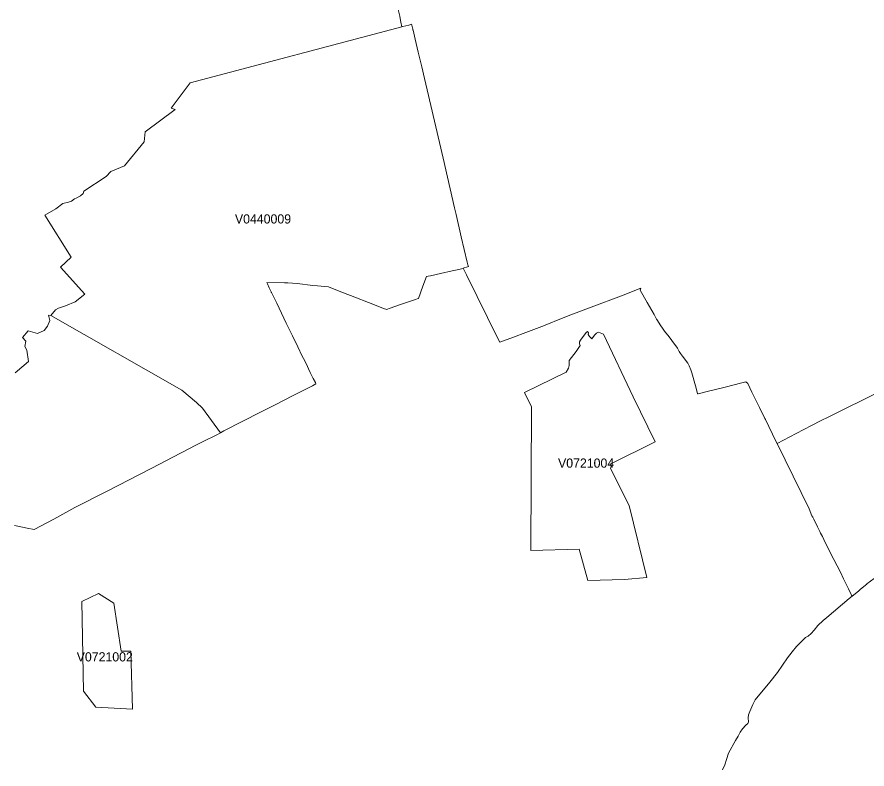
# Model space of a CAD drawing. Extents: x 369010 to 735936, y 6377141 to 6616555.
# Drawn here: x 389842 to 399077, y 6449862 to 6458030 of the extents above; entities that cross this region are included whole.
import ezdxf
from ezdxf.enums import TextEntityAlignment as Align

# ---------------------------------------------------------------- set-up
doc = ezdxf.new("R2010")
doc.units = 0
doc.header["$LTSCALE"] = 40
doc.layers.add('3', color=7, linetype='Continuous', lineweight=13)
doc.layers.add('4', color=7, linetype='Continuous')

msp = doc.modelspace()

# ---------------------------------------------------------------- linework, layer by layer
at = {"layer": '3'}
for points in [[(391559.8, 6457026.29), (391516.76, 6457038.21), (391722.82, 6457316.42), (394024.81, 6457924.48), (394013.06, 6457974.46), (394009.92, 6457990.68), (394000.81, 6458037.69), (393981.12, 6458125.24), (393959.6, 6458222.39), (393924.35, 6458376.31), (393879.17, 6458576.4), (393824.39, 6458815.89), (393782.35, 6459006.38), (393772.91, 6459047.59)], [(394000.81, 6458037.69), (394009.92, 6457990.68), (394013.06, 6457974.46), (394024.81, 6457924.48), (394024.81, 6457924.48), (394032.92, 6457926.3), (394097.63, 6457943.02), (394119.98, 6457949.14), (394129.74, 6457951.29), (394132.39, 6457942.03), (394142.82, 6457896.51), (394144.14, 6457890.88), (394144.97, 6457887.74), (394167.48, 6457790.75), (394201.24, 6457649.25), (394238.81, 6457489.21), (394268.6, 6457363.59), (394298.06, 6457239.46), (394470.51, 6456498.33), (394594.81, 6455955.98), (394612.68, 6455886.3), (394667.63, 6455641.19), (394732.84, 6455368.77), (394741.78, 6455337.16), (394746.57, 6455320.44), (394736.48, 6455316.47), (394690.63, 6455301.08), (394693.45, 6455295.62), (394725.06, 6455230.74), (395068.81, 6454532.64), (395087.18, 6454496.56), (395235.64, 6454551.01), (395370.19, 6454602.82), (395572.27, 6454679.61), (395581.21, 6454684.08), (395757.47, 6454754.25), (395859.09, 6454794.14), (396079.71, 6454878.71), (396409.39, 6455002.34), (396621.4, 6455083.44), (396611.31, 6455063.25), (396687.11, 6454930.68), (396763.41, 6454797.28), (396790.55, 6454749.12), (396794.02, 6454743.5), (396838.55, 6454674.81), (396855.26, 6454650.65), (396877.77, 6454617.88), (396925.77, 6454554.49), (396955.39, 6454517.75), (397017.46, 6454432.02), (397037.48, 6454398.09), (397050.22, 6454375.58), (397073.56, 6454345.29), (397130, 6454269)], [(394024.81, 6457924.48), (394024.81, 6457924.48), (391722.82, 6457316.42), (391516.76, 6457038.21), (391559.8, 6457026.29), (391233.26, 6456784.49), (391225.31, 6456672.61), (391009.33, 6456414.75), (390860.54, 6456352.53), (390811.06, 6456299.4), (390569.58, 6456138.03), (390561.14, 6456111.88), (390530.86, 6456087.39), (390485.18, 6456061.57), (390466.64, 6456053.63), (390434.86, 6456031.12), (390401.1, 6456017.21), (390338.38, 6456005.96), (390264.23, 6455947.7), (390143.41, 6455878.19), (390430.23, 6455423.05), (390313.88, 6455312.5), (390577.36, 6455018.89), (390475.41, 6454934.82), (390368.33, 6454891.12), (390292.37, 6454869.28), (390259.26, 6454848.76), (390209.78, 6454788.51), (391632.78, 6453976.05), (391793.49, 6453842.99), (391858.7, 6453780.1), (392053.33, 6453514.3), (392089.74, 6453534.16), (392493.07, 6453742.2), (392639.21, 6453815.35), (392843.78, 6453918.13), (393052.81, 6454025.54), (393090.54, 6454044.9), (393083.43, 6454058.47), (393060.92, 6454104.15), (393027.98, 6454169.86), (393008.29, 6454209.58), (392986.44, 6454257.74), (392953.84, 6454322.45), (392939.93, 6454347.61), (392892.1, 6454447.57), (392835, 6454567.4), (392767.31, 6454706.09), (392664.2, 6454920.75), (392606.61, 6455038.42), (392604.95, 6455042.06), (392603.79, 6455044.22), (392581.62, 6455089.4), (392561.92, 6455131.77), (392557.12, 6455144.84), (392747.29, 6455141.37), (392784.69, 6455141.53), (392885.32, 6455136.9), (393055.12, 6455114.72), (393107.42, 6455108.93), (393226.42, 6455097.51), (393358.66, 6455045.21), (393390.6, 6455033.13), (393512.08, 6454987.61), (393661.03, 6454928.86), (393742.63, 6454894.77), (393825.21, 6454864.48), (393858.81, 6454852.89), (393867.91, 6454856.04), (393886.45, 6454862.16), (394020.18, 6454909.99), (394160.19, 6454956.5), (394201.57, 6454971.56), (394203.39, 6454973.55), (394251.72, 6455108.27), (394291.94, 6455210.05), (394308.65, 6455213.53), (394335.46, 6455220.15), (394444.7, 6455244.64), (394569.49, 6455271.78), (394641.98, 6455288), (394670.44, 6455294.95), (394690.63, 6455301.08), (394736.48, 6455316.47), (394746.57, 6455320.44), (394741.78, 6455337.16), (394732.84, 6455368.77), (394667.63, 6455641.19), (394612.68, 6455886.3), (394594.81, 6455955.98), (394470.51, 6456498.33), (394298.06, 6457239.46), (394268.6, 6457363.59), (394238.81, 6457489.21), (394201.24, 6457649.25), (394167.48, 6457790.75), (394144.97, 6457887.74), (394144.14, 6457890.88), (394142.82, 6457896.51), (394132.39, 6457942.03)], [(394132.39, 6457942.03), (394129.74, 6457951.29), (394119.98, 6457949.14), (394097.63, 6457943.02), (394032.92, 6457926.3), (394024.81, 6457924.48)], [(389821.51, 6454163.73), (389967.65, 6454288.19), (389950.43, 6454412.65), (389928.75, 6454452.7), (389938.02, 6454508.31), (389903.6, 6454549.19), (389963.84, 6454622.02), (390063.64, 6454593.55), (390136.79, 6454624.17), (390173.86, 6454673.16), (390198.36, 6454732.08), (390185.78, 6454792.98), (390209.78, 6454788.51), (390259.26, 6454848.76), (390292.37, 6454869.28), (390368.33, 6454891.12), (390475.41, 6454934.82), (390577.36, 6455018.89), (390313.88, 6455312.5), (390430.23, 6455423.05), (390143.41, 6455878.19), (390264.23, 6455947.7), (390338.38, 6456005.96), (390401.1, 6456017.21), (390434.86, 6456031.12), (390466.64, 6456053.63), (390485.18, 6456061.57), (390530.86, 6456087.39), (390561.14, 6456111.88), (390569.58, 6456138.03), (390811.06, 6456299.4), (390860.54, 6456352.53), (391009.33, 6456414.75), (391225.31, 6456672.61), (391233.26, 6456784.49), (391559.8, 6457026.29)], [(398265.52, 6451135.18), (398309.88, 6451193.1), (398410.17, 6451291.25), (398436.65, 6451306.14), (398468.76, 6451334.61), (398501.53, 6451370.69), (398541.91, 6451419.68), (398599.01, 6451476.12), (398641.71, 6451509.55), (398882.19, 6451713.94), (398914.96, 6451739.76), (398909.83, 6451749.36), (398902.38, 6451763.26), (398874.24, 6451819.87), (398833.53, 6451904.61), (398822.44, 6451926.95), (398787.85, 6451998.45), (398715.2, 6452138.13), (398623.01, 6452321.68), (398591.56, 6452386.06), (398582.63, 6452404.43), (398573.36, 6452423.29), (398563.76, 6452442.99), (398554.33, 6452462.52), (398539.26, 6452493.14), (398523.87, 6452523.59), (398509.31, 6452552.06), (398497.39, 6452575.23), (398486.47, 6452596.91), (398479.02, 6452611.47), (398449.56, 6452686.94), (398100.02, 6453399.27), (398086.94, 6453424.59), (397973.9, 6453658.12), (397967.78, 6453670.04), (397908.86, 6453788.87), (397873.77, 6453862.02), (397827.27, 6453954.21), (397780.59, 6454050.03), (397759.41, 6454068.4), (397716.38, 6454056.65), (397534.32, 6454010.64), (397342.01, 6453961.32), (397243.2, 6453937.33), (397236.75, 6453935.84), (397229.3, 6453968.77), (397215.23, 6454024.55), (397174.35, 6454166.71), (397164.42, 6454196.34), (397145.89, 6454242.51), (397130, 6454269), (397073.56, 6454345.29), (397050.22, 6454375.58), (397037.48, 6454398.09), (397017.46, 6454432.02), (396955.39, 6454517.75), (396925.77, 6454554.49), (396877.77, 6454617.88), (396855.26, 6454650.65), (396838.55, 6454674.81), (396794.02, 6454743.5), (396790.55, 6454749.12), (396763.41, 6454797.28), (396687.11, 6454930.68), (396611.31, 6455063.25), (396621.4, 6455083.44), (396409.39, 6455002.34), (396079.71, 6454878.71), (395859.09, 6454794.14), (395757.47, 6454754.25), (395581.21, 6454684.08), (395572.27, 6454679.61), (395370.19, 6454602.82), (395235.64, 6454551.01), (395087.18, 6454496.56), (395068.81, 6454532.64), (394725.06, 6455230.74), (394693.45, 6455295.62), (394690.63, 6455301.08), (394670.44, 6455294.95), (394641.98, 6455288), (394569.49, 6455271.78), (394444.7, 6455244.64), (394335.46, 6455220.15), (394308.65, 6455213.53), (394291.94, 6455210.05), (394251.72, 6455108.27), (394203.39, 6454973.55), (394201.57, 6454971.56), (394160.19, 6454956.5), (394020.18, 6454909.99), (393886.45, 6454862.16), (393867.91, 6454856.04), (393858.81, 6454852.89), (393825.21, 6454864.48), (393742.63, 6454894.77), (393661.03, 6454928.86), (393512.08, 6454987.61), (393390.6, 6455033.13), (393358.66, 6455045.21)], [(393358.66, 6455045.21), (393226.42, 6455097.51), (393107.42, 6455108.93), (393055.12, 6455114.72), (392885.32, 6455136.9), (392784.69, 6455141.53), (392747.29, 6455141.37), (392557.12, 6455144.84), (392561.92, 6455131.77), (392581.62, 6455089.4), (392603.79, 6455044.22), (392604.95, 6455042.06), (392606.61, 6455038.42), (392664.2, 6454920.75), (392767.31, 6454706.09), (392835, 6454567.4), (392892.1, 6454447.57), (392939.93, 6454347.61), (392953.84, 6454322.45), (392986.44, 6454257.74), (393008.29, 6454209.58), (393027.98, 6454169.86), (393060.92, 6454104.15), (393083.43, 6454058.47), (393090.54, 6454044.9), (393052.81, 6454025.54), (392843.78, 6453918.13), (392639.21, 6453815.35), (392493.07, 6453742.2), (392089.74, 6453534.16), (392053.33, 6453514.3)], [(391863.16, 6453418.14), (392014.43, 6453492.95), (392053.33, 6453514.3), (391858.7, 6453780.1), (391793.49, 6453842.99), (391632.78, 6453976.05), (390209.78, 6454788.51), (390185.78, 6454792.98), (390198.36, 6454732.08), (390173.86, 6454673.16), (390136.79, 6454624.17), (390063.64, 6454593.55), (389963.84, 6454622.02), (389903.6, 6454549.19), (389938.02, 6454508.31), (389928.75, 6454452.7), (389950.43, 6454412.65), (389967.65, 6454288.19), (389821.51, 6454163.73)], [(397130, 6454269), (397145.89, 6454242.51), (397164.42, 6454196.34), (397174.35, 6454166.71), (397215.23, 6454024.55), (397229.3, 6453968.77), (397236.75, 6453935.84), (397243.2, 6453937.33), (397342.01, 6453961.32), (397534.32, 6454010.64), (397716.38, 6454056.65), (397759.41, 6454068.4), (397780.59, 6454050.03), (397827.27, 6453954.21), (397873.77, 6453862.02), (397908.86, 6453788.87), (397967.78, 6453670.04), (397973.9, 6453658.12), (398086.94, 6453424.59), (398100.02, 6453399.27), (398306.57, 6453507.68), (398472.4, 6453593.57), (398578.32, 6453646.7), (398655.28, 6453685.26), (399230.08, 6453970.76)], [(399230.08, 6453970.76), (398655.28, 6453685.26), (398578.32, 6453646.7), (398472.4, 6453593.57), (398306.57, 6453507.68), (398100.02, 6453399.27), (398449.56, 6452686.94), (398479.02, 6452611.47), (398486.47, 6452596.91), (398497.39, 6452575.23), (398509.31, 6452552.06), (398523.87, 6452523.59), (398539.26, 6452493.14), (398554.33, 6452462.52)], [(392053.33, 6453514.3), (392014.43, 6453492.95), (391863.16, 6453418.14), (391783.89, 6453380.4), (391632.78, 6453300.96), (391527.85, 6453247.34), (391396.94, 6453177.66), (391291.68, 6453121.56), (390819.99, 6452881.08), (390471.94, 6452701.34), (390439.33, 6452684.63), (390241.89, 6452577.21), (390030.37, 6452464.01), (390009.52, 6452467.48), (389972.45, 6452474.6), (389814.89, 6452506.71)], [(389814.89, 6452506.71), (389972.45, 6452474.6), (390009.52, 6452467.48), (390030.37, 6452464.01), (390241.89, 6452577.21), (390439.33, 6452684.63), (390471.94, 6452701.34), (390819.99, 6452881.08), (391291.68, 6453121.56), (391396.94, 6453177.66), (391527.85, 6453247.34), (391632.78, 6453300.96), (391783.89, 6453380.4), (391863.16, 6453418.14)], [(398554.33, 6452462.52), (398563.76, 6452442.99), (398573.36, 6452423.29), (398582.63, 6452404.43), (398591.56, 6452386.06), (398623.01, 6452321.68), (398715.2, 6452138.13), (398787.85, 6451998.45), (398822.44, 6451926.95), (398833.53, 6451904.61), (398874.24, 6451819.87), (398902.38, 6451763.26), (398909.83, 6451749.36), (398914.96, 6451739.76), (398983.48, 6451793.06), (399004.66, 6451814.57), (399005.32, 6451815.07), (399075, 6451871.01), (399076.66, 6451872.33), (399076.66, 6451872.5), (399153.45, 6451930.59)], [(397506.85, 6449854.84), (397531.51, 6449908.79), (397550.38, 6449964.73), (397570.9, 6450034.41), (397646.7, 6450173.43), (397675.33, 6450217.46), (397699, 6450261.65), (397722.83, 6450297.07), (397759.24, 6450338.11), (397781.09, 6450358.3), (397788.04, 6450375.51), (397787.38, 6450418.54), (397789.7, 6450449.16), (397802.28, 6450485.24), (397836.7, 6450564.02), (397863.51, 6450615), (398022.06, 6450807.15), (398102.83, 6450911.25), (398211.24, 6451069.97), (398265.52, 6451135.18)]]:
    msp.add_lwpolyline(points, dxfattribs=at)
for points in [[(395425.64, 6452237.27), (395950.95, 6452248.85), (396044.79, 6451909.74), (396441.67, 6451922.15), (396685.12, 6451944), (396493.63, 6452723.85), (396289.73, 6453124.87), (396296.02, 6453146.71), (396285.1, 6453174.52), (396774.99, 6453415.16), (396537.82, 6453905.55), (396212.28, 6454586.76), (396157.99, 6454605.47), (396139.46, 6454594.54), (396116.12, 6454576.01), (396085.83, 6454532.97), (396062.66, 6454558.46), (396047.27, 6454583.29), (396051.08, 6454600.83), (396040.15, 6454614.73), (396024.76, 6454603.81), (395964.19, 6454520.06), (395954.09, 6454502.19), (395954.09, 6454480.51), (395958.89, 6454461.81), (395918.51, 6454398.25), (395839.4, 6454298.95), (395842.54, 6454244.67), (395834.76, 6454215.21), (395809.28, 6454170.85), (395354.31, 6453952.88), (395431.76, 6453794.66)], [(395425.64, 6452237.27), (395431.76, 6453794.66), (395354.31, 6453952.88), (395809.28, 6454170.85), (395834.76, 6454215.21), (395842.54, 6454244.67), (395839.4, 6454298.95), (395918.51, 6454398.25), (395958.89, 6454461.81), (395954.09, 6454480.51), (395954.09, 6454502.19), (395964.19, 6454520.06), (396024.76, 6454603.81), (396040.15, 6454614.73), (396051.08, 6454600.83), (396047.27, 6454583.29), (396062.66, 6454558.46), (396085.83, 6454532.97), (396116.12, 6454576.01), (396139.46, 6454594.54), (396157.99, 6454605.47), (396212.28, 6454586.76), (396537.82, 6453905.55), (396774.99, 6453415.16), (396285.1, 6453174.52), (396296.02, 6453146.71), (396289.73, 6453124.87), (396493.63, 6452723.85), (396685.12, 6451944), (396441.67, 6451922.15), (396044.79, 6451909.74), (395950.95, 6452248.85)], [(390697.52, 6450535.39), (391098.54, 6450512.88), (391078.34, 6451143.62), (390974.74, 6451141.47), (390892.65, 6451662.97), (390726.15, 6451768.73), (390547.24, 6451679.85), (390562.96, 6450706.69)], [(390697.52, 6450535.39), (390562.96, 6450706.69), (390547.24, 6451679.85), (390726.15, 6451768.73), (390892.65, 6451662.97), (390974.74, 6451141.47), (391078.34, 6451143.62), (391098.54, 6450512.88)]]:
    msp.add_lwpolyline(points, close=True, dxfattribs=at)

# ---------------------------------------------------------------- texts
at = {"layer": '4'}
for s, p in [('V0440009', (392514.7, 6455787.09)), ('V0721004', (396025, 6453134.81)), ('V0721002', (390795.82, 6451030.52))]:
    msp.add_text(s, height=100, dxfattribs=at).set_placement(p, align=Align.CENTER)

doc.saveas('drawing.dxf')
